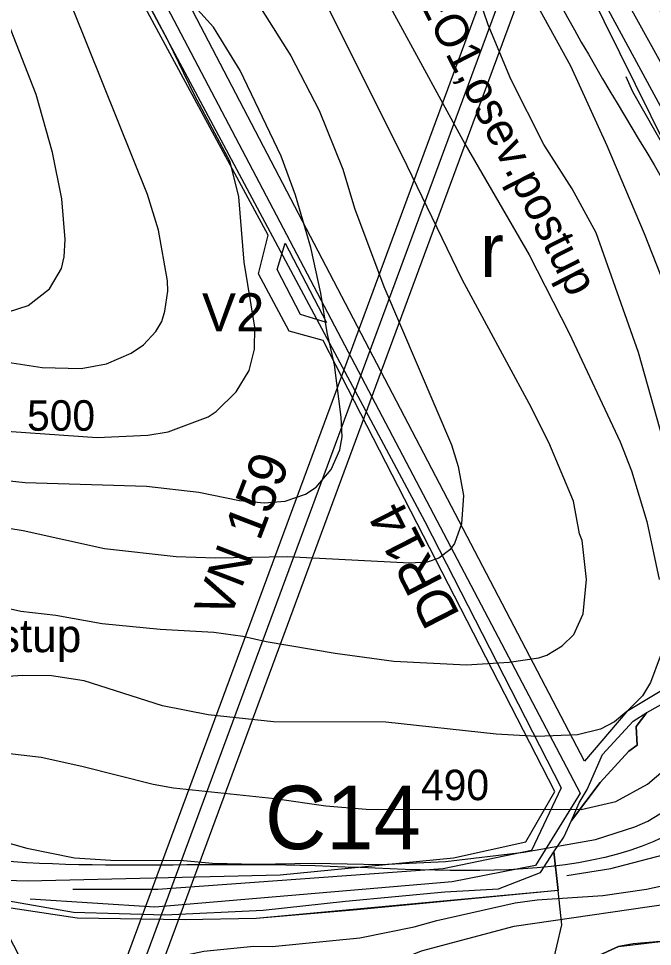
# Model space of a CAD drawing. Extents: x -684583 to -680383, y -1157874 to -1154904.
# Drawn here: x -683375.1 to -683125.8, y -1157689.5 to -1157324.4 of the extents above; entities that cross this region are included whole.
import ezdxf

# ---------------------------------------------------------------- set-up
doc = ezdxf.new("R2010")
doc.units = 0
for name, color, linetype in [('01_DOPRAVA', 7, 'Continuous'), ('01_VRSTEVNICE', 7, 'Continuous'), ('02_KULTURY STAV', 7, 'Continuous'), ('03_PC_NÁVRH', 7, 'Continuous'), ('03_PC_OBJEKTY_NÁVRH', 7, 'Continuous'), ('03_PC_POPIS_NÁVRH', 7, 'Continuous'), ('04_ZPF_OP_ORGAN', 7, 'Continuous'), ('06_BIOGEOGRAFIE', 7, 'Continuous'), ('07_ELEKTRO', 7, 'Continuous'), ('07_OCH_P A POPISY TI', 7, 'Continuous')]:
    doc.layers.add(name, color=color, linetype=linetype)

msp = doc.modelspace()

# ---------------------------------------------------------------- linework, layer by layer
at = {"layer": '01_DOPRAVA'}
msp.add_lwpolyline([(-683054.51, -1157758.92), (-683045.66, -1157702.14), (-683033.32, -1157625.99), (-683033.32, -1157571.3), (-683045.07, -1157508.09), (-683105.62, -1157372.25), (-683148.82, -1157294.04), (-683163.81, -1157254.05), (-683168.81, -1157196.71), (-683165.28, -1157159.67), (-683135.89, -1157075.28), (-683079.46, -1156981.49), (-683035.96, -1156902.98), (-682993.94, -1156817.72), (-682972.78, -1156716.87), (-682952.5, -1156631.31), (-682921.05, -1156497.23), (-682883.43, -1156372.57), (-682870.79, -1156344.34), (-682802.61, -1156200.56), (-682782.62, -1156147.93)], dxfattribs=at)
at = {"layer": '01_VRSTEVNICE'}
for points in [[(-683253.33, -1157274.99), (-683199.55, -1157373.7), (-683174.3, -1157417.35), (-683158.61, -1157448.16), (-683138.5, -1157490.96), (-683134.08, -1157502.37), (-683128.09, -1157522.34), (-683123.24, -1157545.16)], [(-683399.25, -1157551.87), (-683374.15, -1157557.57), (-683360.45, -1157559.14), (-683342.2, -1157562.42), (-683319.37, -1157564.7), (-683298.26, -1157565.84), (-683286.85, -1157567.41), (-683277.72, -1157569.55), (-683250.62, -1157574.12), (-683227.51, -1157577.26), (-683198.98, -1157578.68), (-683182.15, -1157577.68), (-683170.45, -1157575.97), (-683167.32, -1157574.83), (-683161.32, -1157571.26), (-683156.76, -1157566.7), (-683153.05, -1157558.57), (-683151.77, -1157545.16), (-683153.48, -1157529.76), (-683154.48, -1157527.19), (-683156.9, -1157514.35), (-683166.6, -1157491.24), (-683174.3, -1157475.84), (-683200.69, -1157427.05), (-683224.23, -1157378.27), (-683263.17, -1157300.38)], [(-683119.24, -1157498.66), (-683131.37, -1157455.87), (-683147.92, -1157408.79), (-683157.47, -1157391.39), (-683168.6, -1157373.99), (-683181.58, -1157348.31), (-683190.42, -1157326.92), (-683196.27, -1157309.8)], [(-683421.22, -1157501.65), (-683372.44, -1157506.93), (-683324.79, -1157508.36), (-683304.25, -1157510.78), (-683288.28, -1157514.06), (-683278.58, -1157514.92), (-683270.3, -1157514.35), (-683262.32, -1157511.5), (-683258.04, -1157508.79), (-683252.19, -1157501.8), (-683248.76, -1157494.09), (-683247.91, -1157488.96), (-683248.19, -1157481.26), (-683250.9, -1157460.72), (-683253.76, -1157447.88), (-683256.18, -1157432.47), (-683260.18, -1157414.5), (-683266.17, -1157393.96), (-683271.87, -1157378.55), (-683287.99, -1157344.89), (-683298.41, -1157327.77), (-683309.67, -1157315.22)], [(-683392.98, -1157485.82), (-683344.19, -1157489.24), (-683324.22, -1157488.39), (-683316.24, -1157486.96), (-683300.54, -1157481.11), (-683297.41, -1157478.97), (-683289.48, -1157471.25), (-683284.43, -1157462.86), (-683282.29, -1157454.44), (-683282.14, -1157445.88), (-683286.42, -1157420.21), (-683288.42, -1157394.53), (-683291.84, -1157380.84), (-683305.96, -1157354.59), (-683316.24, -1157333.19), (-683325.36, -1157316.08)], [(-683383.28, -1157441.17), (-683371.3, -1157437.32), (-683362.88, -1157430.76), (-683358.17, -1157422.77), (-683357.17, -1157418.21), (-683356.75, -1157411.36), (-683358.03, -1157395.39), (-683361.74, -1157377.13), (-683368.16, -1157354.3), (-683382.57, -1157317.79)], [(-683118.1, -1157436.75), (-683128.94, -1157409.08), (-683143.64, -1157374.56), (-683157.9, -1157343.18), (-683171.45, -1157318.64)], [(-683279.72, -1157320.64), (-683268.02, -1157339.04), (-683256.9, -1157360.58), (-683247.62, -1157383.69), (-683243.06, -1157399.09), (-683231.5, -1157429.9), (-683204.83, -1157492.1), (-683202.26, -1157500.66), (-683200.12, -1157512.07), (-683200.98, -1157523.2), (-683203.69, -1157530.9), (-683205.54, -1157533.46), (-683209.82, -1157536.75), (-683214.39, -1157538.31), (-683221.23, -1157538.74), (-683269.45, -1157536.17), (-683297.69, -1157536.75), (-683313.1, -1157536.17), (-683341.34, -1157533.04), (-683373.29, -1157525.9), (-683398.4, -1157521.91)], [(-683382.99, -1157459.15), (-683365.88, -1157461.71), (-683350.47, -1157462.14), (-683340.48, -1157460.29), (-683330.79, -1157456.01), (-683325.94, -1157452.73), (-683321.09, -1157447.59), (-683318.8, -1157443.6), (-683317.52, -1157439.6), (-683316.38, -1157431.62), (-683316.52, -1157427.62), (-683320.09, -1157407.65), (-683324.37, -1157393.67), (-683353.61, -1157320.92)], [(-683136.36, -1157347.17), (-683133.65, -1157353.16), (-683120.24, -1157376.84), (-683111.97, -1157392.82), (-683097.42, -1157424.77), (-683087.72, -1157450.73), (-683080.59, -1157475.55), (-683075.17, -1157501.23), (-683070.74, -1157533.75), (-683069.03, -1157555.43), (-683069.46, -1157575.4), (-683071.74, -1157590.38)], [(-683122.81, -1157575.4), (-683126.66, -1157585.67), (-683129.8, -1157590.81), (-683135.87, -1157597.03), (-683140.81, -1157601.05), (-683146.2, -1157603.93), (-683155.33, -1157606.21), (-683171.31, -1157606.93), (-683187.29, -1157605.93), (-683230.65, -1157601.22), (-683274.87, -1157601.08), (-683300.54, -1157598.37), (-683318.52, -1157594.8), (-683349.33, -1157584.96), (-683362.17, -1157582.96), (-683373.58, -1157582.82), (-683384.99, -1157583.67)], [(-683410.09, -1157609.92), (-683366.16, -1157615.06), (-683350.18, -1157618.48), (-683322.23, -1157625.61), (-683314.24, -1157627.04), (-683274.3, -1157631.32), (-683254.33, -1157634.17), (-683238.35, -1157635.46), (-683153.91, -1157635.6), (-683140.21, -1157632.46), (-683127.8, -1157625.61), (-683117.1, -1157616.63)], [(-683159.47, -1157661.56), (-683142.21, -1157658.85), (-683121.67, -1157653.43), (-683108.26, -1157648.15), (-683094.14, -1157640.02), (-683084.87, -1157632.6), (-683079.87, -1157626.59), (-683074.6, -1157618.05)], [(-683392.41, -1157645.01), (-683371.87, -1157650.86), (-683353.04, -1157654.57), (-683338.77, -1157655.57), (-683310.24, -1157655.71), (-683298.83, -1157656.71), (-683281.72, -1157657.14), (-683258.89, -1157656.71), (-683232.93, -1157657.28), (-683207.26, -1157656), (-683176.45, -1157652.43), (-683148.2, -1157647.44), (-683132.8, -1157642.45), (-683127.66, -1157640.16), (-683107.12, -1157627.61)], [(-683337.78, -1157704.35), (-683318.09, -1157695.65), (-683309.1, -1157692.8), (-683302.26, -1157691.37), (-683282.57, -1157689.38), (-683275.44, -1157689.52), (-683240.92, -1157686.09), (-683219.52, -1157681.81), (-683210.68, -1157679.25), (-683179.87, -1157672.26), (-683171.17, -1157671.12), (-683145.35, -1157669.4), (-683128.23, -1157666.98), (-683119.1, -1157664.98), (-683103.55, -1157659.71), (-683092.28, -1157653.28), (-683081.44, -1157644.87), (-683076.17, -1157638.74), (-683072.17, -1157632.17)], [(-683224.66, -1157694.51), (-683216.67, -1157691.23), (-683180.15, -1157681.53), (-683111.68, -1157671.54), (-683101.7, -1157669.4), (-683090.15, -1157664.84)]]:
    msp.add_lwpolyline(points, dxfattribs=at)
at = {"layer": '02_KULTURY STAV'}
for points in [[(-683057.49, -1157495.91), (-683068.49, -1157470.25), (-683080.77, -1157444.4), (-683098.71, -1157408.35), (-683114.94, -1157373.25), (-683141.41, -1157324.29), (-683156.77, -1157295.63), (-683162.73, -1157282.87), (-683167.85, -1157267.78), (-683167.85, -1157267.78), (-683174.7, -1157241.69), (-683177.2, -1157220.47), (-683177.86, -1157201.14), (-683157.35, -1157217.4), (-683155.26, -1157236.73), (-683150.78, -1157255.94), (-683140.8, -1157285.4), (-683131.12, -1157306.73), (-683123.39, -1157320.54), (-683093.3, -1157375.73), (-683079.83, -1157403.21), (-683064.17, -1157440.15), (-683054.58, -1157463.9), (-683043.34, -1157491.71)], [(-683157.7, -1157639.96), (-683154.64, -1157633.02), (-683151.53, -1157627.74), (-683145.54, -1157613.99), (-683133.39, -1157600.88), (-683128.09, -1157597.48), (-683132.2, -1157602.9), (-683131.87, -1157610.25), (-683135.08, -1157612.69), (-683146.33, -1157625.01)], [(-683164.55, -1157652.26), (-683162.91, -1157667.49), (-683281.71, -1157678.53), (-683309.57, -1157678.94), (-683352.11, -1157678.28), (-683382.64, -1157673.7), (-683388.32, -1157678.33), (-683410.46, -1157668.82), (-683385.07, -1157670.52), (-683353.46, -1157675.97), (-683317.52, -1157676.97), (-683278.91, -1157675.21), (-683246.58, -1157671.66), (-683207.44, -1157668.02), (-683186.4, -1157666.82), (-683169.92, -1157660.36)], [(-683389.99, -1157681.04), (-683379.08, -1157685.1), (-683373.05, -1157696.8), (-683363.24, -1157701.31), (-683334.67, -1157705.73), (-683313.22, -1157706.54), (-683281.26, -1157705.29), (-683200.33, -1157699.66), (-683165.43, -1157697.75), (-683161.45, -1157681), (-683162.91, -1157667.49), (-683241.98, -1157675.01), (-683281.71, -1157678.53), (-683309.57, -1157678.94), (-683352.11, -1157678.28), (-683382.64, -1157673.7), (-683388.32, -1157678.33)]]:
    msp.add_lwpolyline(points, close=True, dxfattribs=at)
for points in [[(-683165.43, -1157697.75), (-683161.45, -1157681), (-683162.91, -1157667.49), (-683164.55, -1157652.26), (-683160.67, -1157646.41), (-683157.7, -1157639.96), (-683146.33, -1157625.01), (-683135.08, -1157612.69), (-683131.87, -1157610.25), (-683132.2, -1157602.9), (-683128.09, -1157597.48), (-683117.09, -1157591.23)], [(-683155.61, -1157697), (-683139.21, -1157689.44), (-683122.62, -1157687.52), (-683110.28, -1157686.5), (-683097.29, -1157686.54), (-683081.6, -1157689.6), (-683077.6, -1157688.87), (-683073.47, -1157688.22), (-683067.24, -1157685.33), (-683055.55, -1157675.64), (-683048.22, -1157674.26), (-683048.74, -1157678.14), (-683052.69, -1157706.77)], [(-683122.62, -1157687.52), (-683133.39, -1157688.42), (-683139.21, -1157689.44), (-683155.61, -1157697)]]:
    msp.add_lwpolyline(points, dxfattribs=at)
at = {"layer": '03_PC_NÁVRH'}
msp.add_lwpolyline([(-683354.54, -1157220.48), (-683345.16, -1157242.05), (-683331.48, -1157291.73), (-683154.27, -1157629.17), (-683171.81, -1157657.66), (-683204.62, -1157664.04), (-683321.5, -1157674.07), (-683370.49, -1157670.88)], dxfattribs=at)
msp.add_lwpolyline([(-683354.54, -1157220.48), (-683345.16, -1157242.05), (-683331.48, -1157291.73), (-683154.27, -1157629.17), (-683171.81, -1157657.66), (-683204.62, -1157664.04), (-683321.5, -1157674.07), (-683370.49, -1157670.88)], dxfattribs=at)
at = {"layer": '03_PC_OBJEKTY_NÁVRH'}
msp.add_lwpolyline([(-683360.87, -1157230.85), (-683349.98, -1157247.96), (-683337.17, -1157294.27), (-683215.37, -1157522.25), (-683161.67, -1157627.02), (-683173.35, -1157651.75), (-683208.18, -1157658.94), (-683320.31, -1157667.04), (-683353.8, -1157667.04)], dxfattribs=at)
msp.add_lwpolyline([(-683254.06, -1157444.06), (-683264.18, -1157440.86), (-683273.4, -1157423.11), (-683270.32, -1157412.77)], close=True, dxfattribs=at)
at = {"layer": '04_ZPF_OP_ORGAN'}
msp.add_lwpolyline([(-683343.12, -1157216.48), (-683255.77, -1157147.12), (-683212.14, -1157111.99), (-683188, -1157100.46), (-683171.81, -1157095.24), (-683160.28, -1157100.46), (-683176.2, -1157149.05), (-683182.23, -1157222.89), (-683169.61, -1157275.32), (-683083.46, -1157449.64), (-683050.81, -1157531.17), (-683043.68, -1157605.57), (-683055.75, -1157649.76), (-683061.24, -1157640.16), (-683077.15, -1157575.37), (-683110.35, -1157581.68), (-683135.87, -1157597.03), (-683152.6, -1157616.55), (-683323.54, -1157289.05), (-683339.45, -1157238.26)], close=True, dxfattribs=at)
msp.add_lwpolyline([(-683424.61, -1157662.07), (-683371.42, -1157663.67), (-683272.2, -1157661.28), (-683204.03, -1157654.59), (-683175.69, -1157648.37), (-683164.22, -1157628.45), (-683255.31, -1157451.1), (-683268.69, -1157447.44), (-683280.8, -1157424.81), (-683276.97, -1157409.67), (-683337.49, -1157297.34)], dxfattribs=at)
at = {"layer": '06_BIOGEOGRAFIE'}
for points in [[(-683605.53, -1156693.94), (-683552.15, -1156773.17), (-683505.66, -1156862.74), (-683385.12, -1156876.52), (-683240.48, -1156867.91), (-682983.91, -1156935.09), (-682923.69, -1156998.38), (-682921.97, -1157094.84), (-682923.69, -1157198.19), (-682892.7, -1157272.26), (-682746.33, -1157329.1), (-682572.41, -1157337.72), (-682417.44, -1157289.49), (-682386.73, -1157266.62)], [(-683662.04, -1156787.77), (-683658.6, -1156877.34), (-683631.05, -1156927.29), (-683541.5, -1156975.52), (-683489.85, -1157028.92), (-683414.08, -1157027.2), (-683362.42, -1157025.48), (-683360.7, -1157063.37), (-683464.02, -1157132.27), (-683493.29, -1157163.28), (-683474.35, -1157189.11), (-683407.19, -1157171.89), (-683317.65, -1157115.05), (-683269.44, -1157104.71), (-683207.44, -1157173.61), (-683186.78, -1157259.74), (-683105.85, -1157416.48), (-683069.69, -1157530.17), (-683073.13, -1157580.12), (-683097.24, -1157628.35), (-683264.27, -1157657.63), (-683431.3, -1157647.3), (-683531.17, -1157605.96), (-683636.21, -1157542.23), (-683651.71, -1157521.56), (-683682.7, -1157519.83), (-683708.53, -1157528.45), (-683818.74, -1157547.39), (-683870.4, -1157518.11), (-683980.6, -1157521.56), (-684052.92, -1157490.55), (-684171.74, -1157400.98), (-684213.07, -1157375.14), (-684250.95, -1157388.92), (-684249.23, -1157437.15), (-684237.17, -1157466.44), (-684170.02, -1157518.11), (-684097.7, -1157562.9), (-684011.6, -1157605.96), (-683953.05, -1157602.51), (-683891.06, -1157626.63), (-683835.96, -1157619.74), (-683789.47, -1157599.07), (-683713.7, -1157578.4), (-683625.88, -1157592.18), (-683551.84, -1157667.97), (-683445.07, -1157736.87), (-683346.92, -1157771.32), (-683179.89, -1157767.87), (-683081.74, -1157773.04), (-683016.71, -1157810.65), (-682999.16, -1157844)]]:
    msp.add_spline(points, degree=3, dxfattribs=at)
at = {"layer": '07_ELEKTRO'}
msp.add_lwpolyline([(-683353.35, -1157770.3), (-683109.07, -1157109.08), (-683073.5, -1157019.42), (-683054.68, -1156978.22), (-683011.49, -1156911.63), (-683020.57, -1156816.29), (-682818.44, -1155857.57), (-682314.17, -1155533.82)], dxfattribs=at)
msp.add_lwpolyline([(-683353.35, -1157770.3), (-683109.07, -1157109.08), (-683073.5, -1157019.42), (-683054.68, -1156978.22), (-683011.49, -1156911.63), (-683020.57, -1156816.29), (-682818.44, -1155857.57), (-682314.17, -1155533.82)], dxfattribs=at)
at = {"layer": '07_OCH_P A POPISY TI'}
for p, q in [((-683115.61, -1157106.58), (-683359.92, -1157767.87)), ((-683346.78, -1157772.73), (-683102.53, -1157111.58))]:
    msp.add_line(p, q, dxfattribs=at)

# ---------------------------------------------------------------- texts
at = {"layer": '01_VRSTEVNICE'}
for s, p in [('500', (-683371.77, -1157486.59)), ('490', (-683216.84, -1157631.93))]:
    msp.add_text(s, height=12, dxfattribs=at).set_placement(p)
at = {"layer": '02_KULTURY STAV'}
msp.add_text('r', height=21, dxfattribs=at).set_placement((-683193.58, -1157426.05))
at = {"layer": '03_PC_OBJEKTY_NÁVRH'}
msp.add_text('V2', height=15, dxfattribs=at).set_placement((-683302.98, -1157447.51))
msp.add_text('DR14', height=15, rotation=117.1006, dxfattribs=at).set_placement((-683201.29, -1157559.02))
at = {"layer": '03_PC_POPIS_NÁVRH'}
msp.add_text('C14', height=25, dxfattribs=at).set_placement((-683278.23, -1157651.21))
at = {"layer": '04_ZPF_OP_ORGAN'}
msp.add_text('PEO1,osev.postup', height=13, rotation=297.0292, dxfattribs=at).set_placement((-683224.11, -1157305.45))
msp.add_text('PEO1,osev.postup', height=13, dxfattribs=at).set_placement((-683495.36, -1157573.69))
at = {"layer": '07_OCH_P A POPISY TI'}
msp.add_text('VN 159', height=15, rotation=68.9657, dxfattribs=at).set_placement((-683292.3, -1157561.54))

doc.saveas('drawing.dxf')
